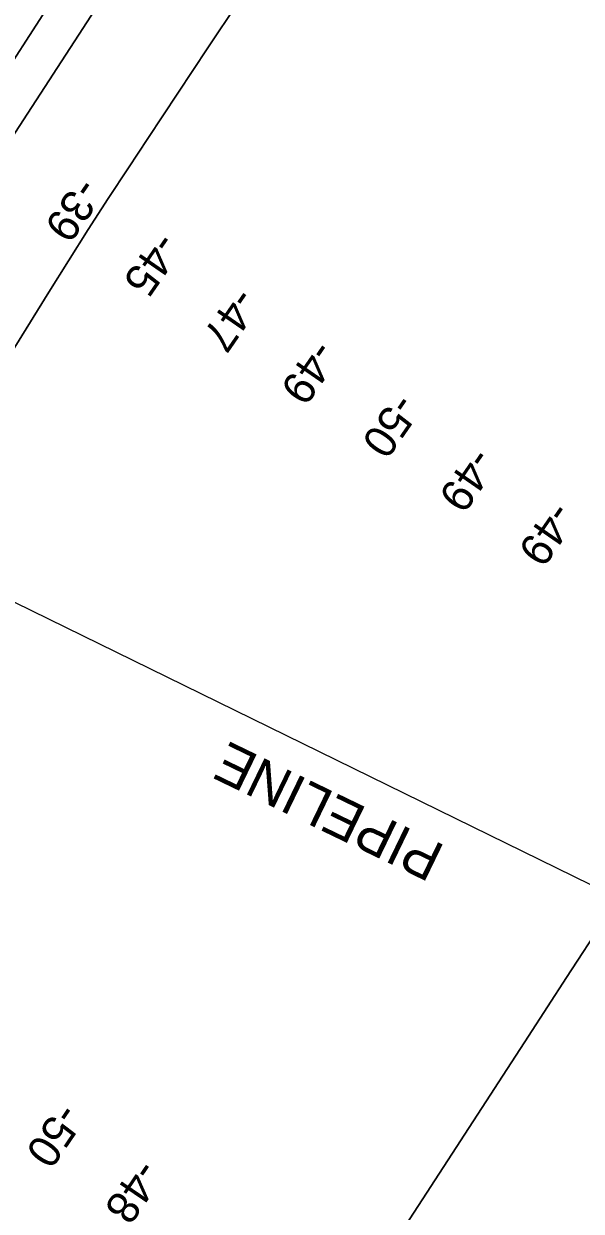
# Model space of a CAD drawing. Extents: x 3905714 to 3926767, y 183354 to 205755.
# Drawn here: x 3914961 to 3915542, y 190284 to 191522 of the extents above; entities that cross this region are included whole.
import ezdxf

# ---------------------------------------------------------------- set-up
doc = ezdxf.new("R2010")
doc.units = 0
for name, color, linetype in [('V-RIVR-RANG', 7, 'Continuous'), ('V-TOPO-DPTH', 7, 'Continuous'), ('V-TOPO-MINR', 7, 'Continuous'), ('V-UTIL-IDEN', 7, 'Continuous'), ('V-UTIL-LINE', 7, 'Continuous')]:
    doc.layers.add(name, color=color, linetype=linetype)

msp = doc.modelspace()

# ---------------------------------------------------------------- linework, layer by layer
at = {"layer": 'V-TOPO-DPTH'}
for points in [[(3914008.8, 190002.7), (3914466.4, 190645.5), (3914472.1, 190656), (3914478.1, 190666.4), (3914484.1, 190676.7), (3914490.8, 190688.1), (3914493.5, 190692.7), (3914496.3, 190697.3), (3914499.2, 190701.8), (3914502.1, 190706.3), (3914517.4, 190729.8), (3914528, 190746), (3914538.5, 190762.3), (3914549, 190778.6), (3914559.5, 190794.9), (3914922.7, 191362.7), (3914924.4, 191365.5), (3914926.2, 191368.3), (3914928, 191371.1), (3914929.8, 191373.9), (3915305.6, 191952.3)], [(3914008.8, 190002.7), (3914466.4, 190645.5), (3914472.1, 190656), (3914478.1, 190666.4), (3914484.1, 190676.7), (3914490.8, 190688.1), (3914493.5, 190692.7), (3914496.3, 190697.3), (3914499.2, 190701.8), (3914502.1, 190706.3), (3914517.4, 190729.8), (3914528, 190746), (3914538.5, 190762.3), (3914549, 190778.6), (3914559.5, 190794.9), (3914922.7, 191362.7), (3914924.4, 191365.5), (3914926.2, 191368.3), (3914928, 191371.1), (3914929.8, 191373.9), (3915305.6, 191952.3)], [(3914152.9, 190258.9), (3914175.2, 190291.7), (3914196.7, 190324.9), (3914217.7, 190358.6), (3914238.4, 190392.3), (3914259.2, 190426), (3914280.4, 190459.5), (3914301.7, 190493), (3914413.5, 190666.9), (3914430.9, 190693.8), (3914448.4, 190720.6), (3914466.1, 190747.4), (3914483.8, 190774.1), (3914586.8, 190928.4), (3914638, 191005.4), (3914689.1, 191082.6), (3914739.8, 191159.9), (3914790.4, 191237.4), (3914863.5, 191349.7), (3914877.4, 191371.1), (3914891.3, 191392.4), (3914905.1, 191413.8), (3914919, 191435.2), (3914998.2, 191557.6)], [(3914998.2, 191557.6), (3914919, 191435.2), (3914905.1, 191413.8), (3914891.3, 191392.4), (3914877.4, 191371.1), (3914863.5, 191349.7), (3914790.4, 191237.4), (3914739.8, 191159.9), (3914689.1, 191082.6), (3914638, 191005.4), (3914586.8, 190928.4), (3914483.8, 190774.1), (3914466.1, 190747.4), (3914448.4, 190720.6), (3914430.9, 190693.8), (3914413.5, 190666.9), (3914301.7, 190493), (3914280.4, 190459.5), (3914259.2, 190426), (3914238.4, 190392.3), (3914217.7, 190358.6), (3914196.7, 190324.9), (3914175.2, 190291.7), (3914152.9, 190258.9)], [(3915184.9, 191543.8), (3915153.3, 191496.6), (3915121.9, 191449.4), (3915090.6, 191402.1), (3915070.5, 191371.6), (3915049.4, 191339.5), (3915028.5, 191307.1), (3915007.9, 191274.6), (3914987.5, 191242), (3914789, 190921.7)], [(3914789, 190921.7), (3914987.5, 191242), (3915007.9, 191274.6), (3915028.5, 191307.1), (3915049.4, 191339.5), (3915070.5, 191371.6), (3915090.6, 191402.1), (3915121.9, 191449.4), (3915153.3, 191496.6), (3915184.9, 191543.8)], [(3915566.8, 190588.7), (3915527, 190527.5), (3915487.3, 190466.4), (3915314.8, 190200.6)], [(3915566.8, 190588.7), (3915527, 190527.5), (3915487.3, 190466.4), (3915314.8, 190200.6)]]:
    msp.add_lwpolyline(points, dxfattribs=at)
at = {"layer": 'V-TOPO-MINR'}
for points in [[(3915305.6, 191952.3), (3914929.8, 191373.9), (3914928, 191371.1), (3914926.2, 191368.3), (3914924.4, 191365.5), (3914922.7, 191362.7), (3914559.5, 190794.9), (3914549, 190778.6), (3914538.5, 190762.3), (3914528, 190746), (3914517.4, 190729.8), (3914502.1, 190706.3), (3914499.2, 190701.8), (3914496.3, 190697.3), (3914493.5, 190692.7), (3914490.8, 190688.1), (3914484.1, 190676.7), (3914478.1, 190666.4), (3914472.1, 190656), (3914466.4, 190645.5), (3914008.8, 190002.7)], [(3914998.2, 191557.6), (3914919, 191435.2), (3914905.1, 191413.8), (3914891.3, 191392.4), (3914877.4, 191371.1), (3914863.5, 191349.7), (3914790.4, 191237.4), (3914739.8, 191159.9), (3914689.1, 191082.6), (3914638, 191005.4), (3914586.8, 190928.4), (3914483.8, 190774.1), (3914466.1, 190747.4), (3914448.4, 190720.6), (3914430.9, 190693.8), (3914413.5, 190666.9), (3914301.7, 190493), (3914280.4, 190459.5), (3914259.2, 190426), (3914238.4, 190392.3), (3914217.7, 190358.6), (3914196.7, 190324.9), (3914175.2, 190291.7), (3914152.9, 190258.9)], [(3915184.9, 191543.8), (3915153.3, 191496.6), (3915121.9, 191449.4), (3915090.6, 191402.1), (3915070.5, 191371.6), (3915049.4, 191339.5), (3915028.5, 191307.1), (3915007.9, 191274.6), (3914987.5, 191242), (3914789, 190921.7)], [(3915314.8, 190200.6), (3915487.3, 190466.4), (3915527, 190527.5), (3915566.8, 190588.7)]]:
    msp.add_lwpolyline(points, dxfattribs=at)
at = {"layer": 'V-UTIL-LINE'}
msp.add_line((3914355, 191211.2), (3916411.1, 190203.8), dxfattribs=at)

# ---------------------------------------------------------------- texts
at = {"layer": 'V-RIVR-RANG'}
for s, rotation, p in [('-39', 235.3801, (3915018.6, 191363.5)), ('-45', 235.3801, (3915100.6, 191306.6)), ('-47', 235.3801, (3915182.2, 191248.9)), ('-49', 235.3801, (3915264.4, 191194.1)), ('-50', 235.3801, (3915349.1, 191138.5)), ('-49', 235.3801, (3915429.3, 191082)), ('-49', 235.3801, (3915512.1, 191025.7)), ('-50', 235.7854, (3914998.6, 190398.8)), ('-48', 235.7854, (3915080.7, 190340.2))]:
    msp.add_text(s, height=33.5, rotation=rotation, dxfattribs=at).set_placement(p)
at = {"layer": 'V-UTIL-IDEN'}
msp.add_text('PIPELINE', height=42, rotation=154.1907, dxfattribs=at).set_placement((3915402, 190664.3))

doc.saveas('drawing.dxf')
